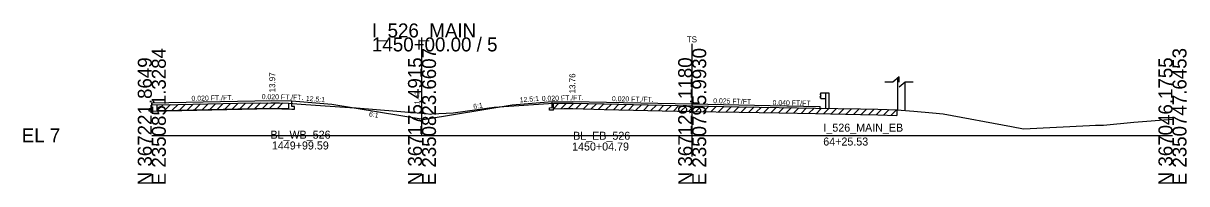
# Model space of a CAD drawing. Extents: x -170 to 2527928, y -10 to 1619750.
# Drawn here: x 4974.3 to 5206.8, y 9490.3 to 9522.4 of the extents above; entities that cross this region are included whole.
import ezdxf

# ---------------------------------------------------------------- set-up
doc = ezdxf.new("R2010")
doc.units = 0
for name, color, linetype in [('Default', 7, 'Continuous'), ('RD_GPK_XS_Cell', 7, 'Continuous'), ('RD_PD_NOISE-WALL-GM', 7, 'Continuous'), ('RD_XS_Base', 7, 'Continuous'), ('RD_XS_EarthShd', 7, 'Continuous'), ('RD_XS_ExGround', 7, 'Continuous'), ('RD_XS_ExPaveRet', 7, 'Continuous'), ('RD_XS_GR', 7, 'Continuous'), ('RD_XS_MatchLine', 7, 'Continuous'), ('RD_XS_Pave', 7, 'Continuous'), ('RD_XS_PaveShd', 7, 'Continuous'), ('RD_XS_TieSlope', 7, 'Continuous'), ('RD_XS_TX_Elev_EX', 7, 'Continuous'), ('RD_XS_TX_Slope', 7, 'Continuous'), ('RD_XS_TX_Station', 7, 'Continuous')]:
    doc.layers.add(name, color=color, linetype=linetype)

msp = doc.modelspace()

# ---------------------------------------------------------------- linework, layer by layer
at = {"layer": 'Default'}
for p, q in [((5149.35, 9511.69), (5148.1, 9510.66)), ((5149.35, 9510.66), (5149.35, 9511.69)), ((5148.1, 9510.66), (5146.52, 9510.66)), ((5150.6, 9510.66), (5149.35, 9509.64)), ((5152.2, 9510.66), (5150.6, 9510.66))]:
    msp.add_line(p, q, dxfattribs=at)
at = {"layer": 'RD_GPK_XS_Cell'}
for p, q in [((5054, 9500), (5054, 9519.6)), ((5000, 9500), (5054, 9500)), ((5054, 9500), (5108, 9500)), ((5108, 9500), (5204, 9500))]:
    msp.add_line(p, q, dxfattribs=at)
at = {"layer": 'RD_PD_NOISE-WALL-GM'}
for p, q in [((5149.1, 9505.1), (5149.1, 9511.48)), ((5150.6, 9504.97), (5150.6, 9510.66))]:
    msp.add_line(p, q, dxfattribs=at)
at = {"layer": 'RD_XS_Base'}
for p, q in [((5000, 9505.36), (5000, 9506.49)), ((5028, 9505.76), (5028, 9506.89)), ((5080, 9505.54), (5080, 9506.68)), ((5080.25, 9505.05), (5080.25, 9506.45)), ((4999.5, 9505.35), (5000, 9505.36)), ((4999.5, 9504.85), (4999.5, 9505.35)), ((5000, 9504.86), (4999.5, 9504.85)), ((5000, 9504.86), (5024, 9505.34)), ((5024, 9505.34), (5028, 9505.26)), ((5028.5, 9505.75), (5028, 9505.76)), ((5028, 9505.26), (5028.5, 9505.25)), ((5028.5, 9505.25), (5028.5, 9505.75)), ((5079.5, 9505.53), (5080, 9505.54)), ((5079.5, 9505.03), (5079.5, 9505.53)), ((5080.25, 9505.05), (5079.5, 9505.03)), ((5133.56, 9505.44), (5133.56, 9505.79))]:
    msp.add_line(p, q, dxfattribs=at)
at = {"layer": 'RD_XS_EarthShd'}
for p, q in [((5028, 9506.89), (5036, 9506.25)), ((5080, 9506.68), (5072, 9506.04))]:
    msp.add_line(p, q, dxfattribs=at)
at = {"layer": 'RD_XS_ExGround'}
msp.add_lwpolyline([(5000, 9506.09), (5005.18, 9506.19), (5011.29, 9506.31), (5017.17, 9506.42), (5023.77, 9506.53), (5025.55, 9506.5), (5027.29, 9506.47), (5029.87, 9506.26), (5034.66, 9505.94), (5039.57, 9505.59), (5040.83, 9505.5), (5053.01, 9504.49), (5054, 9504.41), (5054.8, 9504.34), (5055.67, 9504.27), (5055.99, 9504.29), (5060.25, 9504.5), (5067.4, 9505.5), (5068.41, 9505.63), (5070.37, 9505.76), (5080.25, 9506.45), (5082.34, 9506.46), (5084.13, 9506.46), (5090.39, 9506.3), (5096.25, 9506.15), (5102.01, 9506.03), (5108.16, 9505.9), (5117.4, 9505.73), (5125.38, 9505.6), (5132.64, 9505.46), (5141.65, 9505.29), (5145.13, 9505.21), (5148.9, 9505.12), (5152.31, 9504.83), (5156, 9504.51), (5158.16, 9504.33), (5171.79, 9501.77), (5174.2, 9501.3), (5187.44, 9501.97), (5188.58, 9502.04), (5190.2, 9502.06), (5196.28, 9502.66), (5204, 9503.22)], dxfattribs=at)
at = {"layer": 'RD_XS_ExPaveRet'}
for p, q in [((5002.6, 9505.02), (5003.75, 9506.16)), ((5004.1, 9505.05), (5005.24, 9506.19)), ((5005.6, 9505.08), (5006.74, 9506.22)), ((5007.1, 9505.11), (5008.24, 9506.25)), ((5008.6, 9505.14), (5009.74, 9506.28)), ((5010.1, 9505.17), (5011.24, 9506.31)), ((5011.6, 9505.2), (5012.74, 9506.34)), ((5013.1, 9505.22), (5014.24, 9506.36)), ((5014.6, 9505.25), (5015.74, 9506.39)), ((5016.1, 9505.28), (5017.24, 9506.42)), ((5017.6, 9505.3), (5018.74, 9506.45)), ((5019.1, 9505.33), (5020.24, 9506.47)), ((5020.6, 9505.36), (5021.74, 9506.5)), ((5022.1, 9505.38), (5023.24, 9506.52)), ((5023.6, 9505.41), (5024.71, 9506.52)), ((5025.1, 9505.39), (5026.2, 9506.49)), ((5027.29, 9506.47), (5027.29, 9505.35)), ((5080.25, 9505.33), (5081.38, 9506.45)), ((5080.25, 9505.33), (5080.25, 9506.45)), ((5081.75, 9505.33), (5082.88, 9506.46)), ((5083.25, 9505.34), (5084.37, 9506.45)), ((5084.75, 9505.32), (5085.85, 9506.41)), ((5086.25, 9505.28), (5087.35, 9506.38)), ((5087.75, 9505.25), (5088.85, 9506.34)), ((5089.25, 9505.21), (5090.35, 9506.3)), ((5090.75, 9505.17), (5091.85, 9506.26)), ((5092.25, 9505.13), (5093.35, 9506.23)), ((5093.75, 9505.09), (5094.85, 9506.19)), ((5095.25, 9505.05), (5096.35, 9506.15)), ((5001.1, 9504.99), (5002.25, 9506.13)), ((5001.1, 9504.99), (5001.1, 9506.11)), ((5001.1, 9504.99), (5005.18, 9505.07)), ((5005.18, 9505.07), (5011.29, 9505.19)), ((5011.29, 9505.19), (5017.17, 9505.3)), ((5017.17, 9505.3), (5023.77, 9505.41)), ((5023.77, 9505.41), (5025.55, 9505.38)), ((5025.55, 9505.38), (5027.29, 9505.35)), ((5080.25, 9505.33), (5082.34, 9505.34)), ((5082.34, 9505.34), (5084.13, 9505.34)), ((5084.13, 9505.34), (5090.39, 9505.18)), ((5090.39, 9505.18), (5096.25, 9505.03)), ((5096.25, 9505.03), (5102.01, 9504.91)), ((5096.75, 9505.02), (5097.85, 9506.12)), ((5098.25, 9504.99), (5099.35, 9506.09)), ((5099.75, 9504.96), (5100.85, 9506.06)), ((5101.25, 9504.93), (5102.35, 9506.03)), ((5102.01, 9504.91), (5108.16, 9504.78)), ((5102.75, 9504.9), (5103.85, 9505.99)), ((5104.25, 9504.86), (5105.35, 9505.96)), ((5105.75, 9504.83), (5106.85, 9505.93)), ((5107.25, 9504.8), (5108.35, 9505.9)), ((5108.16, 9504.78), (5117.4, 9504.61)), ((5108.75, 9504.77), (5109.85, 9505.87)), ((5110.25, 9504.74), (5111.35, 9505.84)), ((5111.75, 9504.71), (5112.85, 9505.82)), ((5113.25, 9504.69), (5114.35, 9505.79)), ((5114.75, 9504.66), (5115.85, 9505.76)), ((5116.25, 9504.63), (5117.35, 9505.73)), ((5117.4, 9504.61), (5125.38, 9504.48)), ((5117.75, 9504.6), (5118.86, 9505.71)), ((5119.25, 9504.58), (5120.36, 9505.68)), ((5120.75, 9504.55), (5121.86, 9505.66)), ((5122.25, 9504.53), (5123.36, 9505.63)), ((5123.75, 9504.5), (5124.86, 9505.61)), ((5125.25, 9504.48), (5126.35, 9505.58)), ((5125.38, 9504.48), (5132.64, 9504.34)), ((5126.75, 9504.45), (5127.85, 9505.55)), ((5128.25, 9504.42), (5129.35, 9505.52)), ((5129.75, 9504.39), (5130.85, 9505.49)), ((5131.25, 9504.36), (5132.35, 9505.46)), ((5132.64, 9504.34), (5141.65, 9504.17)), ((5132.75, 9504.33), (5133.85, 9505.43)), ((5134.25, 9504.31), (5135.35, 9505.41)), ((5135.75, 9504.28), (5136.85, 9505.38)), ((5137.25, 9504.25), (5138.35, 9505.35)), ((5138.75, 9504.22), (5139.85, 9505.32)), ((5140.25, 9504.19), (5141.35, 9505.29)), ((5141.65, 9504.17), (5145.13, 9504.09)), ((5141.75, 9504.17), (5142.85, 9505.26)), ((5143.25, 9504.13), (5144.35, 9505.23)), ((5144.75, 9504.09), (5145.85, 9505.19)), ((5145.13, 9504.09), (5148.9, 9504)), ((5146.25, 9504.06), (5147.35, 9505.15)), ((5147.75, 9504.02), (5148.85, 9505.12)), ((5148.9, 9505.12), (5148.9, 9504))]:
    msp.add_line(p, q, dxfattribs=at)
at = {"layer": 'RD_XS_GR'}
for p, q in [((5133.73, 9507.35), (5133.73, 9508.51)), ((5133.73, 9508.51), (5134.64, 9508.51)), ((5134.64, 9508.51), (5135.31, 9508.51)), ((5134.64, 9508.51), (5134.64, 9505.42)), ((5135.31, 9508.51), (5135.31, 9505.41)), ((5133.73, 9508.44), (5133.56, 9508.24)), ((5133.56, 9508.24), (5133.56, 9508.19)), ((5133.56, 9508.19), (5133.73, 9507.99)), ((5133.56, 9507.67), (5133.73, 9507.87)), ((5133.56, 9507.62), (5133.56, 9507.67)), ((5133.73, 9507.42), (5133.56, 9507.62)), ((5133.73, 9507.35), (5134.64, 9507.35))]:
    msp.add_line(p, q, dxfattribs=at)
at = {"layer": 'RD_XS_MatchLine'}
msp.add_line((5108.01, 9495.76), (5108.01, 9518.35), dxfattribs=at)
at = {"layer": 'RD_XS_Pave'}
for p, q in [((5000, 9506.49), (5024, 9506.97)), ((5084, 9506.76), (5108, 9506.28)), ((5108, 9506.28), (5123.56, 9505.97))]:
    msp.add_line(p, q, dxfattribs=at)
at = {"layer": 'RD_XS_PaveShd'}
for p, q in [((5000, 9506.49), (5000, 9506.09)), ((5024, 9506.97), (5028, 9506.89)), ((5080, 9506.68), (5084, 9506.76)), ((5123.56, 9505.97), (5133.56, 9505.79))]:
    msp.add_line(p, q, dxfattribs=at)
at = {"layer": 'RD_XS_TieSlope'}
for p in [(5036, 9506.25), (5072, 9506.04)]:
    msp.add_line(p, (5054.64, 9503.15), dxfattribs=at)

# ---------------------------------------------------------------- texts
at = {"layer": 'RD_GPK_XS_Cell'}
for s, p in [('I_526_MAIN', (5044, 9519.6)), ('1450+00.00 / 5', (5044, 9516.8)), ('EL 7', (4974, 9498.6))]:
    msp.add_text(s, height=2.8, dxfattribs=at).set_placement(p)
for s, p in [('E 2350851.3284', (5002.8, 9490)), ('N 367175.4915', (5054, 9490)), ('E 2350823.6607', (5056.8, 9490)), ('N 367129.1180', (5108, 9490)), ('E 2350795.9930', (5110.8, 9490)), ('N 367046.1755', (5204, 9490)), ('E 2350747.6453', (5206.8, 9490)), ('N 367221.8649', (5000, 9490))]:
    msp.add_text(s, height=2.8, rotation=90, dxfattribs=at).set_placement(p)
at = {"layer": 'RD_XS_MatchLine'}
msp.add_text('TS', height=1.2, dxfattribs=at).set_placement((5106.92, 9518.62))
at = {"layer": 'RD_XS_TX_Elev_EX'}
msp.add_text('11.41', height=1, rotation=90, dxfattribs=at).set_placement((5053.5, 9505.41))
at = {"layer": 'RD_XS_TX_Slope'}
for s, rotation, p in [('0.020 FT./FT.', 1.1458, (5007.94, 9506.9)), ('0.020 FT./FT.', 358.8542, (5021.95, 9507.26)), ('12.5:1', 355.4261, (5030.75, 9506.93)), ('6:1', 9.4623, (5064.33, 9505.26)), ('12.5:1', 4.5739, (5073.58, 9506.59)), ('0.020 FT./FT.', 1.1458, (5077.94, 9506.89)), ('0.020 FT./FT.', 358.8542, (5091.95, 9506.85)), ('0.025 FT/FT', 358.5427, (5112.19, 9506.44)), ('0.040 FT/FT', 359.1102, (5124.06, 9506.06)), ('6:1', 350.5446, (5043.35, 9503.81))]:
    msp.add_text(s, height=1, rotation=rotation, dxfattribs=at).set_placement(p)
at = {"layer": 'RD_XS_TX_Station'}
for s, p in [(' 13.97', (5024.66, 9508.15)), (' 13.76', (5084.66, 9507.93))]:
    msp.add_text(s, height=1.2, rotation=90, dxfattribs=at).set_placement(p)
for s, p in [('I_526_MAIN_EB', (5134.23, 9500.74)), ('BL_WB_526', (5023.71, 9499.33)), ('BL_EB_526', (5084.2, 9499.12)), ('64+25.53', (5134.2, 9497.96)), ('1449+99.59', (5024, 9497.17)), ('1450+04.79', (5084, 9496.96))]:
    msp.add_text(s, height=1.6, dxfattribs=at).set_placement(p)

doc.saveas('drawing.dxf')
